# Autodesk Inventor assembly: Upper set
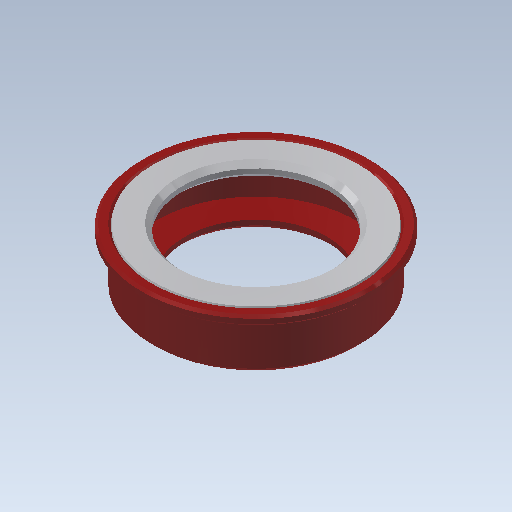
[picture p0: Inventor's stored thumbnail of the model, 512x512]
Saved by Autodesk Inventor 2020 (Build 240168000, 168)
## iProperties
Created: 2017-09
Part Number: Upper set
Material: Ogólny
Document SubType Name: Assembly
Designer: Tomasz
Sending System: SolidWorks 2017
Last Author: Tomasz
Last Saved: 2017-09-27
Author: Tomasz
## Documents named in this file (3)
- C:\Users\bruno\Documents\1-Cours-2020-21\1STI2D-2020-21\IT\6. Antivol\Inventor-Antivol\INVENTOR 2018_Steel Hardtail B+\Upper set.iam
- C:\Users\bruno\Documents\1-Cours-2020-21\1STI2D-2020-21\IT\6. Antivol\Inventor-Antivol\INVENTOR 2018_Steel Hardtail B+\upper cup.ipt
- C:\Users\bruno\Documents\1-Cours-2020-21\1STI2D-2020-21\IT\6. Antivol\Inventor-Antivol\INVENTOR 2018_Steel Hardtail B+\insert.ipt
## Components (2 placed, 2 different names)
1. upper cup:1
2. insert:1
